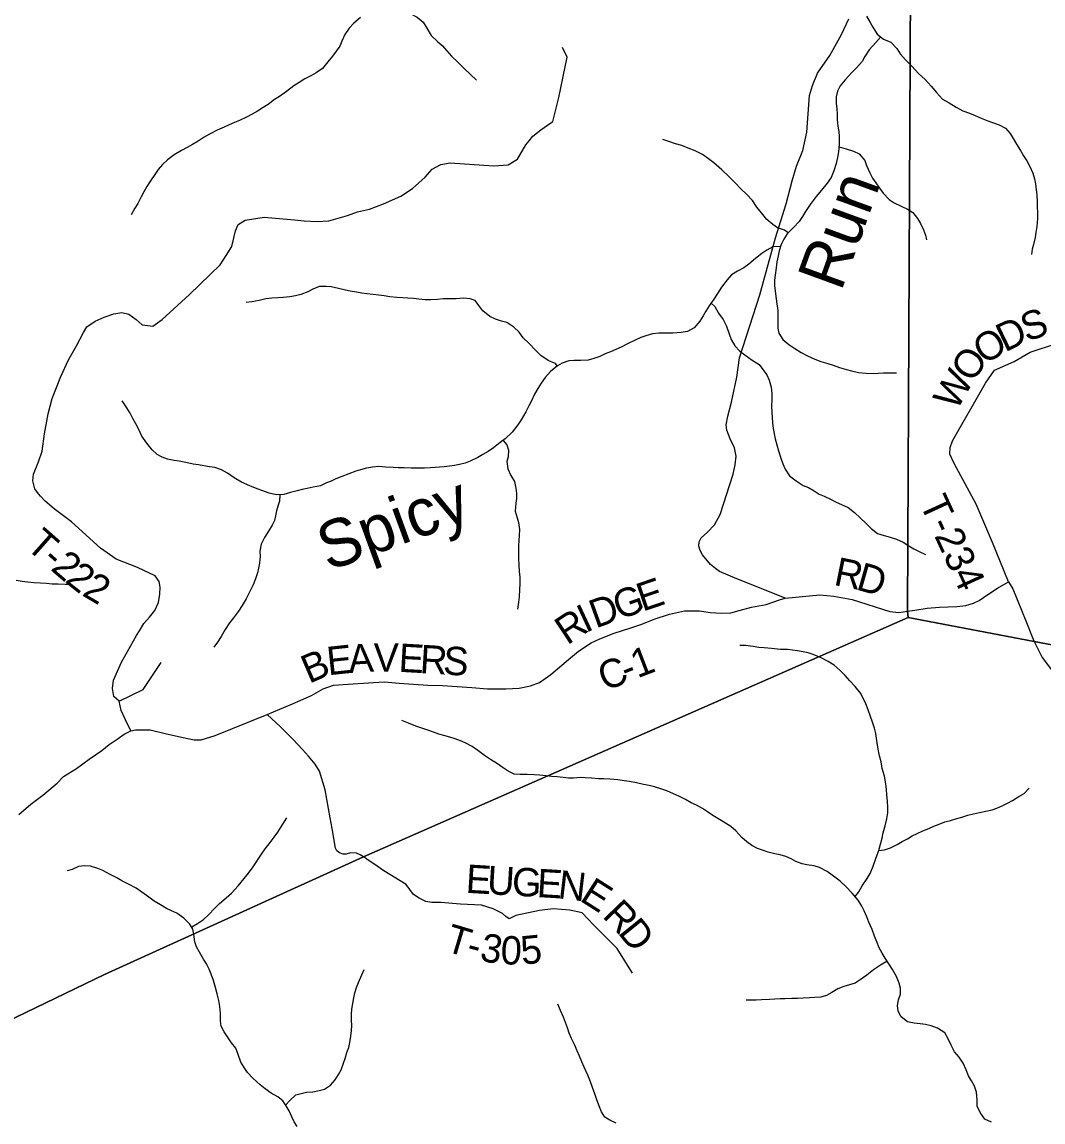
# Model space of a CAD drawing. Extents: x 1578669 to 1989827, y 208020 to 553079.
# Drawn here: x 1757093 to 1767882, y 384601 to 396225 of the extents above; entities that cross this region are included whole.
import ezdxf

# ---------------------------------------------------------------- set-up
doc = ezdxf.new("R2010")
doc.units = 0
for name, color, linetype in [('GM_X_County_Road', 7, 'Continuous'), ('GM_X_County_Road_Text', 7, 'Continuous'), ('GM_X_Minor_River', 7, 'Continuous'), ('GM_X_Minor_River_Text', 7, 'Continuous'), ('GM_X_Township', 7, 'Continuous'), ('GM_X_Township_Road', 7, 'Continuous'), ('GM_X_Township_Road_Text', 7, 'Continuous'), ('GM_X_Township_ROW', 7, 'Continuous')]:
    doc.layers.add(name, color=color, linetype=linetype)

msp = doc.modelspace()

# ---------------------------------------------------------------- linework, layer by layer
at = {"layer": 'GM_X_County_Road'}
for points in [[(1766527, 390011), (1766658, 390031), (1766789, 390041), (1766973, 390047), (1767065, 390058), (1767149, 390084), (1767208, 390113), (1767298, 390174), (1767402, 390241), (1767517, 390309), (1767563, 390236), (1767699, 389896), (1767767, 389729)], [(1757061, 387849), (1757185, 387958), (1757312, 388055), (1757463, 388183), (1757532, 388253), (1757669, 388337), (1757804, 388434), (1757935, 388527), (1758014, 388590), (1758099, 388647), (1758171, 388701), (1758215, 388722), (1758242, 388734), (1758294, 388746), (1758446, 388746), (1758619, 388702), (1758797, 388664), (1758911, 388640), (1758987, 388639), (1759135, 388684), (1759685, 388906), (1759952, 389021), (1760151, 389109), (1760277, 389178), (1760384, 389217), (1760540, 389229), (1760808, 389246), (1760923, 389251), (1761079, 389239), (1761381, 389218), (1761535, 389212), (1761847, 389192), (1762012, 389178), (1762207, 389178), (1762347, 389186), (1762465, 389209), (1762562, 389246), (1762682, 389329), (1762868, 389489), (1762973, 389578), (1763106, 389663), (1763199, 389708), (1763349, 389765), (1763516, 389819), (1763643, 389862), (1763773, 389914), (1763936, 389967), (1764094, 390001), (1764253, 390001), (1764366, 389986), (1764484, 389978), (1764583, 389983), (1764671, 390006), (1764801, 390041), (1764956, 390069), (1765098, 390120), (1765159, 390135), (1765341, 390155), (1765523, 390171), (1765673, 390159), (1765867, 390121), (1766264, 389996), (1766358, 389985), (1766452, 389999), (1766527, 390011)], [(1767767, 389729), (1767788, 389678), (1767875, 389511), (1767972, 389378), (1768053, 389292), (1768114, 389256), (1768276, 389190), (1768452, 389138), (1768590, 389116), (1768649, 389123), (1768926, 389190), (1769160, 389267), (1769361, 389336)]]:
    msp.add_lwpolyline(points, dxfattribs=at)
at = {"layer": 'GM_X_Minor_River'}
for points in [[(1760817, 396602), (1760844, 396579), (1760894, 396526), (1760956, 396470), (1761011, 396418), (1761077, 396384), (1761131, 396349), (1761203, 396311), (1761269, 396277), (1761332, 396222), (1761372, 396158), (1761416, 396082), (1761484, 396017), (1761537, 395973), (1761583, 395921), (1761633, 395865), (1761699, 395802), (1761765, 395734), (1761896, 395609)], [(1760669, 396273), (1760599, 396211), (1760549, 396161), (1760505, 396093), (1760474, 396021), (1760450, 395969), (1760414, 395915), (1760374, 395863), (1760326, 395803), (1760268, 395735), (1760202, 395689), (1760151, 395659), (1760083, 395625), (1760021, 395585), (1759965, 395549), (1759887, 395492), (1759813, 395436), (1759761, 395406), (1759693, 395352), (1759641, 395322), (1759581, 395284), (1759525, 395252), (1759467, 395220), (1759392, 395184), (1759340, 395163), (1759282, 395137), (1759230, 395115), (1759154, 395083), (1759074, 395041), (1759018, 395009), (1758956, 394967), (1758894, 394930), (1758840, 394900), (1758778, 394866), (1758700, 394822), (1758632, 394770), (1758576, 394718), (1758533, 394666), (1758495, 394614), (1758451, 394546), (1758413, 394486), (1758379, 394430), (1758353, 394378), (1758316, 394308), (1758286, 394256), (1758248, 394188)], [(1766017, 396287), (1766055, 396219), (1766083, 396169), (1766128, 396097), (1766198, 396042), (1766274, 396012), (1766338, 395946), (1766373, 395887), (1766429, 395825), (1766497, 395759), (1766565, 395682), (1766638, 395616), (1766700, 395546), (1766756, 395479), (1766821, 395409), (1766891, 395369), (1766963, 395324), (1767035, 395286), (1767105, 395262), (1767165, 395238), (1767230, 395207), (1767298, 395179), (1767350, 395161), (1767418, 395137), (1767486, 395102), (1767536, 395048), (1767567, 394992), (1767603, 394934), (1767645, 394867), (1767677, 394809), (1767711, 394759), (1767744, 394697), (1767774, 394626), (1767794, 394566), (1767802, 394516), (1767811, 394452), (1767817, 394400), (1767821, 394324), (1767821, 394272), (1767825, 394209), (1767824, 394149), (1767818, 394065), (1767808, 394001), (1767798, 393947), (1767780, 393875), (1767769, 393825), (1767761, 393767)], [(1766167, 396067), (1766116, 396009), (1766046, 395929), (1766000, 395859), (1765971, 395809), (1765911, 395741), (1765861, 395691), (1765791, 395613), (1765739, 395551), (1765711, 395495), (1765698, 395435), (1765696, 395367), (1765702, 395306), (1765706, 395250), (1765708, 395192), (1765715, 395124), (1765723, 395066), (1765729, 395014), (1765729, 394932), (1765722, 394853), (1765712, 394793), (1765698, 394731), (1765672, 394651), (1765644, 394583), (1765603, 394521), (1765541, 394449), (1765485, 394381), (1765421, 394295), (1765373, 394223), (1765340, 394171), (1765306, 394115), (1765244, 394053), (1765180, 393987), (1765144, 393929), (1765116, 393873), (1765095, 393807), (1765083, 393755), (1765071, 393689), (1765063, 393627), (1765053, 393551), (1765046, 393495), (1765046, 393441), (1765056, 393353), (1765064, 393300), (1765070, 393248), (1765081, 393176), (1765081, 393124), (1765079, 393056), (1765079, 392990), (1765089, 392936), (1765132, 392869), (1765196, 392817), (1765260, 392775), (1765328, 392734), (1765392, 392698), (1765471, 392662), (1765533, 392638), (1765607, 392615), (1765665, 392597), (1765733, 392573), (1765805, 392553), (1765857, 392540), (1765931, 392522), (1766012, 392514), (1766088, 392512), (1766140, 392513), (1766196, 392517), (1766334, 392517)], [(1765189, 393997), (1765150, 394024), (1765078, 394050), (1765026, 394084), (1764963, 394138), (1764907, 394207), (1764859, 394269), (1764811, 394337), (1764750, 394404), (1764694, 394460), (1764626, 394530), (1764561, 394591), (1764489, 394663), (1764403, 394735), (1764347, 394780), (1764284, 394826), (1764208, 394864), (1764134, 394893), (1764064, 394919), (1764000, 394939), (1763928, 394961), (1763864, 394984)], [(1765727, 394907), (1765803, 394883), (1765880, 394859), (1765938, 394831), (1765998, 394762), (1766018, 394710), (1766053, 394630), (1766081, 394576), (1766117, 394526), (1766155, 394469), (1766193, 394417), (1766256, 394349), (1766308, 394314), (1766384, 394278), (1766450, 394248), (1766508, 394210), (1766555, 394147), (1766589, 394097), (1766621, 394027), (1766639, 393973), (1766651, 393923)], [(1765109, 393851), (1765028, 393850), (1764964, 393812), (1764912, 393780), (1764843, 393724), (1764773, 393666), (1764721, 393626), (1764653, 393592), (1764591, 393554), (1764545, 393500), (1764485, 393421), (1764442, 393357), (1764404, 393295), (1764356, 393227), (1764320, 393169), (1764292, 393119), (1764256, 393063), (1764197, 392993), (1764127, 392953), (1764059, 392943), (1763971, 392935), (1763905, 392937), (1763824, 392938), (1763756, 392928), (1763684, 392910), (1763634, 392890), (1763574, 392864), (1763497, 392826), (1763423, 392787), (1763369, 392765), (1763311, 392741), (1763257, 392717), (1763199, 392691), (1763137, 392669), (1763077, 392652), (1762997, 392648), (1762929, 392648), (1762873, 392644), (1762801, 392620), (1762751, 392592), (1762679, 392533), (1762621, 392469), (1762579, 392409), (1762543, 392351), (1762510, 392291), (1762476, 392221), (1762450, 392169), (1762416, 392105), (1762368, 392021), (1762333, 391967), (1762271, 391889), (1762197, 391821), (1762147, 391781), (1762075, 391725), (1762019, 391687), (1761963, 391653), (1761909, 391623), (1761829, 391583), (1761775, 391562), (1761715, 391550), (1761663, 391540), (1761609, 391532), (1761553, 391524), (1761409, 391513), (1761347, 391511), (1761287, 391511), (1761207, 391509), (1761131, 391512), (1761071, 391514), (1761015, 391516), (1760935, 391522), (1760863, 391528), (1760795, 391521), (1760733, 391509), (1760669, 391493), (1760619, 391477), (1760547, 391449), (1760471, 391422), (1760411, 391396), (1760361, 391374), (1760311, 391356), (1760249, 391324), (1760171, 391310), (1760105, 391296), (1760053, 391283), (1760001, 391271), (1759931, 391253), (1759859, 391233), (1759781, 391227), (1759705, 391246), (1759639, 391270), (1759579, 391292), (1759500, 391322), (1759414, 391361), (1759334, 391409), (1759264, 391458), (1759200, 391494), (1759132, 391516), (1759075, 391524), (1759015, 391534), (1758957, 391545)], [(1762749, 392591), (1762729, 392615), (1762661, 392643), (1762580, 392697), (1762516, 392760), (1762454, 392826), (1762390, 392886), (1762345, 392946), (1762291, 392999), (1762215, 393051), (1762159, 393065), (1762095, 393084), (1762038, 393114), (1761964, 393172), (1761922, 393230), (1761882, 393281), (1761830, 393301), (1761758, 393307), (1761680, 393301), (1761622, 393299), (1761545, 393298), (1761485, 393292), (1761409, 393288), (1761355, 393288), (1761285, 393297), (1761231, 393303), (1761169, 393307), (1761117, 393309), (1761055, 393315), (1760979, 393322), (1760921, 393330), (1760865, 393338), (1760805, 393344), (1760737, 393352), (1760683, 393359), (1760627, 393369), (1760562, 393379), (1760510, 393391), (1760436, 393409), (1760360, 393426), (1760308, 393430), (1760238, 393430), (1760172, 393406), (1760114, 393374), (1760038, 393347), (1759982, 393331), (1759922, 393321), (1759852, 393315), (1759798, 393311), (1759734, 393308), (1759668, 393298), (1759598, 393282), (1759522, 393268), (1759460, 393262)], [(1764375, 393254), (1764414, 393218), (1764454, 393148), (1764501, 393080), (1764537, 393010), (1764567, 392931), (1764587, 392871), (1764626, 392803), (1764678, 392747), (1764730, 392706), (1764810, 392652), (1764884, 392604), (1764923, 392553), (1764963, 392495), (1764989, 392441), (1765009, 392365), (1765016, 392299), (1765016, 392234), (1765014, 392164), (1765016, 392100), (1765020, 392046), (1765025, 391990), (1765031, 391930), (1765053, 391820), (1765088, 391693), (1765110, 391615), (1765134, 391555), (1765156, 391501), (1765203, 391430), (1765273, 391376), (1765349, 391326), (1765403, 391306), (1765465, 391271), (1765517, 391237), (1765568, 391215), (1765644, 391180), (1765698, 391152), (1765754, 391126), (1765822, 391096), (1765890, 391041), (1765951, 390985), (1766015, 390925), (1766067, 390873), (1766135, 390820), (1766203, 390800), (1766268, 390782), (1766334, 390760), (1766404, 390727), (1766466, 390689), (1766518, 390657), (1766572, 390631), (1766642, 390598)], [(1758957, 391545), (1758903, 391553), (1758825, 391571), (1758753, 391585), (1758701, 391592), (1758631, 391606), (1758573, 391626), (1758521, 391654), (1758468, 391705), (1758412, 391775), (1758360, 391847), (1758330, 391913), (1758297, 391980), (1758265, 392036), (1758237, 392090), (1758193, 392158), (1758150, 392221)], [(1762176, 391804), (1762217, 391755), (1762235, 391700), (1762230, 391630), (1762218, 391580), (1762228, 391504), (1762260, 391432), (1762296, 391368), (1762313, 391299), (1762319, 391243), (1762317, 391191), (1762311, 391139), (1762306, 391055), (1762326, 390987), (1762340, 390935), (1762350, 390862), (1762348, 390800), (1762343, 390746), (1762341, 390688), (1762341, 390556), (1762343, 390484), (1762348, 390418), (1762354, 390360), (1762354, 390287), (1762350, 390227), (1762347, 390149), (1762341, 390093), (1762329, 390021)], [(1759817, 391230), (1759813, 391161), (1759795, 391109), (1759782, 391059), (1759770, 391007), (1759760, 390957), (1759736, 390907), (1759698, 390845), (1759656, 390779), (1759621, 390707), (1759607, 390633), (1759609, 390577), (1759601, 390505), (1759593, 390455), (1759580, 390403), (1759562, 390342), (1759536, 390278), (1759504, 390214), (1759460, 390128), (1759421, 390060), (1759379, 389998), (1759327, 389927), (1759287, 389875), (1759241, 389805), (1759196, 389731), (1759160, 389671), (1759120, 389619)], [(1757030, 390325), (1757094, 390316), (1757152, 390310), (1757218, 390302), (1757288, 390298), (1757352, 390294), (1757410, 390289), (1757476, 390287), (1757550, 390285), (1757616, 390281)], [(1765896, 386984), (1765936, 387034), (1765972, 387098), (1766025, 387174), (1766055, 387226), (1766087, 387306), (1766119, 387396), (1766146, 387470), (1766164, 387538), (1766182, 387600), (1766194, 387656), (1766216, 387730), (1766231, 387806), (1766241, 387867), (1766243, 387927), (1766239, 387991), (1766233, 388057), (1766230, 388115), (1766222, 388173), (1766208, 388257), (1766184, 388336), (1766171, 388406), (1766153, 388472), (1766143, 388522), (1766135, 388582), (1766124, 388656), (1766114, 388706), (1766100, 388763), (1766082, 388825), (1766058, 388887), (1766033, 388955), (1766011, 389019), (1765957, 389128), (1765896, 389202), (1765840, 389264), (1765790, 389319), (1765738, 389373), (1765674, 389429), (1765613, 389469), (1765537, 389506), (1765453, 389542), (1765399, 389560), (1765347, 389568), (1765289, 389581), (1765235, 389587), (1765183, 389593), (1765109, 389595), (1765012, 389604), (1764934, 389610), (1764880, 389616), (1764820, 389624), (1764740, 389637), (1764678, 389635)], [(1763660, 388167), (1763586, 388184), (1763512, 388198), (1763456, 388208), (1763388, 388216), (1763306, 388223), (1763242, 388227), (1763184, 388229), (1763110, 388235), (1763045, 388238), (1762991, 388240), (1762921, 388236), (1762869, 388236), (1762811, 388240), (1762747, 388247), (1762687, 388251), (1762631, 388259), (1762561, 388265), (1762505, 388269), (1762431, 388274), (1762357, 388274), (1762295, 388278), (1762229, 388308), (1762168, 388351), (1762116, 388387), (1762044, 388431), (1761980, 388475), (1761910, 388526), (1761851, 388568), (1761777, 388608), (1761725, 388630), (1761671, 388649), (1761615, 388667), (1761551, 388685), (1761499, 388699), (1761443, 388720), (1761392, 388738), (1761328, 388760), (1761254, 388784), (1761178, 388817), (1761108, 388843)], [(1767337, 384599), (1767269, 384631), (1767218, 384700), (1767188, 384770), (1767186, 384834), (1767180, 384916), (1767157, 384980), (1767127, 385036), (1767095, 385089), (1767071, 385151), (1767039, 385223), (1766996, 385287), (1766948, 385344), (1766912, 385414), (1766876, 385488), (1766845, 385542), (1766769, 385593), (1766699, 385617), (1766639, 385633), (1766585, 385637), (1766521, 385644), (1766449, 385660), (1766384, 385712), (1766352, 385774), (1766346, 385832), (1766356, 385893), (1766376, 385953), (1766375, 386015), (1766363, 386067), (1766333, 386139), (1766293, 386211), (1766261, 386262), (1766214, 386332), (1766184, 386384), (1766148, 386448), (1766128, 386498), (1766103, 386565), (1766077, 386635), (1766043, 386713), (1766019, 386769), (1765992, 386831), (1765966, 386882), (1765928, 386946), (1765866, 387020), (1765801, 387085), (1765739, 387147), (1765653, 387209), (1765601, 387248), (1765519, 387292), (1765464, 387308), (1765388, 387320), (1765336, 387328), (1765272, 387355), (1765220, 387383), (1765164, 387407), (1765104, 387425), (1765050, 387436), (1764978, 387454), (1764919, 387472), (1764865, 387492), (1764805, 387523), (1764753, 387563), (1764701, 387609), (1764635, 387679), (1764584, 387722), (1764528, 387760), (1764464, 387798), (1764394, 387840), (1764336, 387879), (1764285, 387913), (1764219, 387949), (1764165, 387975), (1764105, 388010), (1764035, 388044), (1763979, 388068), (1763907, 388100), (1763854, 388119), (1763778, 388143), (1763720, 388157), (1763660, 388167)], [(1766145, 387469), (1766208, 387478), (1766272, 387500), (1766342, 387532), (1766394, 387564), (1766450, 387595), (1766500, 387625), (1766554, 387651), (1766612, 387677), (1766676, 387703), (1766730, 387727), (1766784, 387747), (1766846, 387772), (1766906, 387786), (1766972, 387808), (1767024, 387824), (1767088, 387842), (1767148, 387856), (1767210, 387871), (1767278, 387887), (1767344, 387901), (1767396, 387917), (1767456, 387945), (1767506, 387969), (1767560, 387999), (1767628, 388042), (1767682, 388074), (1767736, 388128)], [(1758886, 386662), (1758947, 386700), (1759011, 386740), (1759065, 386790), (1759131, 386860), (1759181, 386910), (1759249, 386970), (1759305, 387020), (1759378, 387097), (1759442, 387173), (1759488, 387231), (1759536, 387299), (1759625, 387431), (1759663, 387487), (1759705, 387541), (1759757, 387611), (1759795, 387665), (1759849, 387749), (1759890, 387817)], [(1758673, 386833), (1758621, 386858), (1758556, 386896), (1758488, 386934), (1758434, 386976), (1758360, 387031), (1758298, 387073), (1758219, 387115), (1758149, 387148), (1758095, 387182), (1758025, 387216), (1757947, 387258), (1757893, 387281), (1757816, 387303), (1757754, 387307), (1757690, 387301), (1757624, 387271), (1757570, 387256)], [(1760001, 384553), (1759969, 384603), (1759943, 384655), (1759915, 384719), (1759884, 384772), (1759850, 384824), (1759796, 384866), (1759726, 384906), (1759662, 384953), (1759611, 384995), (1759533, 385065), (1759475, 385124), (1759441, 385176), (1759405, 385232), (1759378, 385314), (1759354, 385383), (1759306, 385439), (1759270, 385491), (1759229, 385553), (1759197, 385613), (1759189, 385670), (1759189, 385752), (1759182, 385820), (1759172, 385884), (1759156, 385956), (1759138, 386024), (1759117, 386095), (1759091, 386165), (1759069, 386217), (1759041, 386273), (1759011, 386323), (1758968, 386396), (1758938, 386452), (1758920, 386506), (1758908, 386586), (1758899, 386640), (1758867, 386692), (1758803, 386755), (1758729, 386807), (1758673, 386833)], [(1766235, 386301), (1766166, 386260), (1766091, 386210), (1766021, 386152), (1765951, 386102), (1765899, 386070), (1765839, 386051), (1765779, 386033), (1765715, 386009), (1765649, 385971), (1765595, 385939), (1765535, 385919), (1765467, 385916), (1765413, 385914), (1765349, 385910), (1765289, 385906), (1765227, 385906), (1765155, 385903), (1765103, 385901), (1765049, 385899), (1764991, 385897), (1764907, 385891), (1764851, 385889), (1764799, 385888), (1764745, 385888)], [(1759878, 384780), (1759924, 384830), (1759988, 384890), (1760044, 384903), (1760100, 384915), (1760166, 384921), (1760234, 384933), (1760290, 384949), (1760354, 384991), (1760402, 385048), (1760438, 385102), (1760464, 385154), (1760491, 385223), (1760509, 385273), (1760525, 385335), (1760545, 385387), (1760557, 385443), (1760568, 385507), (1760574, 385569), (1760578, 385621), (1760574, 385673), (1760576, 385741), (1760580, 385793), (1760589, 385853), (1760599, 385913), (1760611, 385967), (1760627, 386024), (1760649, 386074), (1760710, 386214)], [(1763370, 384590), (1763304, 384620), (1763253, 384654), (1763215, 384709), (1763195, 384761), (1763167, 384837), (1763147, 384899), (1763122, 384967), (1763102, 385026), (1763072, 385096), (1763032, 385182), (1763009, 385238), (1762983, 385298), (1762959, 385353), (1762931, 385421), (1762900, 385483), (1762876, 385539), (1762856, 385597), (1762836, 385654), (1762816, 385708), (1762785, 385780), (1762755, 385848)]]:
    msp.add_lwpolyline(points, dxfattribs=at)
at = {"layer": 'GM_X_Township'}
for points in [[(1766495, 399541), (1766452, 389999), (1766457, 389933), (1760700, 387403), (1757963, 386161), (1756930, 385658), (1755534, 385267), (1753423, 384881), (1752837, 384779), (1752746, 384750), (1752525, 384707), (1752358, 384675), (1752267, 384661), (1743250, 382913)], [(1769444, 389364), (1767788, 389678), (1766457, 389933), (1766452, 389999), (1766495, 399541)], [(1743250, 382913), (1752267, 384661), (1752358, 384675), (1752525, 384707), (1752746, 384750), (1752837, 384779), (1753423, 384881), (1755534, 385267), (1756930, 385658), (1757963, 386161), (1760700, 387403), (1766457, 389933), (1767788, 389678), (1769444, 389364)]]:
    msp.add_lwpolyline(points, dxfattribs=at)
at = {"layer": 'GM_X_Township_Road'}
for points in [[(1762453, 394970), (1762453, 394970), (1762491, 395017), (1762574, 395084), (1762645, 395134), (1762701, 395173), (1762739, 395313), (1762766, 395427), (1762853, 395854), (1762806, 395955)], [(1757270, 391237), (1757269, 391238), (1757228, 391293), (1757207, 391376), (1757214, 391446), (1757269, 391576), (1757305, 391690), (1757331, 391872), (1757369, 392084), (1757413, 392246), (1757503, 392480), (1757585, 392656), (1757669, 392803), (1757744, 392943), (1757779, 393005), (1757866, 393064), (1757960, 393107), (1758063, 393142), (1758149, 393155), (1758221, 393136), (1758298, 393081), (1758364, 393026), (1758476, 393009), (1758574, 393080), (1758863, 393347), (1759187, 393659), (1759252, 393758), (1759309, 393854), (1759349, 394018), (1759378, 394086), (1759450, 394131), (1759653, 394163), (1759971, 394135), (1760076, 394124), (1760212, 394118), (1760335, 394125), (1760531, 394179), (1760640, 394220), (1760764, 394246), (1760913, 394303), (1761096, 394385), (1761219, 394466), (1761352, 394585), (1761427, 394670), (1761518, 394719), (1761618, 394738), (1762076, 394705), (1762232, 394717), (1762329, 394776), (1762418, 394928), (1762453, 394970)], [(1767517, 390309), (1767347, 390724), (1767177, 391129), (1766945, 391561), (1766899, 391658), (1766900, 391728), (1766925, 391798), (1767275, 392408), (1767369, 392544), (1767578, 392638), (1767748, 392736), (1768026, 392827), (1768248, 392923), (1768484, 393083), (1768705, 393239), (1768872, 393349), (1769009, 393352), (1769921, 393351)], [(1758242, 388734), (1758187, 388851), (1758142, 388948), (1758118, 389047), (1758065, 389099), (1758048, 389182), (1758059, 389270), (1758145, 389459), (1758302, 389742), (1758335, 389792), (1758382, 389870), (1758439, 389937), (1758495, 390007), (1758536, 390091), (1758549, 390177), (1758554, 390251), (1758543, 390311), (1758501, 390372), (1758314, 390462), (1758087, 390549), (1757922, 390664), (1757615, 390944), (1757434, 391080), (1757339, 391160), (1757288, 391213), (1757270, 391237)], [(1765159, 390135), (1764868, 390251), (1764648, 390340), (1764465, 390418), (1764423, 390450)], [(1758118, 389047), (1758373, 389171), (1758565, 389456)], [(1760741, 387376), (1760732, 387382), (1760700, 387403), (1760668, 387425), (1760629, 387442), (1760565, 387445), (1760517, 387430), (1760487, 387430), (1760448, 387444), (1760419, 387468), (1760404, 387495), (1760372, 387702), (1760348, 387816), (1760298, 388110), (1760236, 388307), (1760191, 388382), (1760121, 388467), (1760058, 388536), (1759957, 388642), (1759826, 388776), (1759685, 388906)], [(1763546, 386174), (1763383, 386435), (1763133, 386684), (1763012, 386812), (1762882, 386838), (1762707, 386854), (1762563, 386837), (1762311, 386782), (1762241, 386747), (1762205, 386773), (1762169, 386804), (1762071, 386853), (1761949, 386891), (1761727, 386903), (1761518, 386922), (1761424, 386921), (1761362, 386932), (1761290, 386967), (1761230, 387005), (1761154, 387110), (1760918, 387255), (1760810, 387330), (1760741, 387376)]]:
    msp.add_lwpolyline(points, dxfattribs=at)
at = {"layer": 'GM_X_Township_ROW'}
msp.add_lwpolyline([(1764423, 390450), (1764368, 390491), (1764285, 390595), (1764259, 390639), (1764246, 390687), (1764250, 390733), (1764269, 390773), (1764338, 390833), (1764410, 390912), (1764470, 391022), (1764608, 391448), (1764629, 391544), (1764640, 391636), (1764623, 391724), (1764578, 391821), (1764541, 391910), (1764534, 391968), (1764551, 392060), (1764592, 392208), (1764647, 392472), (1764674, 392677), (1764889, 393342), (1765057, 393944), (1765169, 394302), (1765230, 394546), (1765278, 394700), (1765343, 394868), (1765386, 395062), (1765414, 395447), (1765445, 395553), (1765500, 395683), (1765630, 395872), (1765753, 396093), (1765831, 396257)], dxfattribs=at)

# ---------------------------------------------------------------- texts
at = {"layer": 'GM_X_County_Road_Text'}
for s, rotation, p in [('R', 348.6227, (1765661, 390278)), ('D', 344.0621, (1765896, 390231)), ('E', 18.8754, (1763651, 389992)), ('G', 19.4487, (1763402, 389905)), ('D', 19.8888, (1763155, 389815)), ('R', 33.5764, (1762855, 389635)), ('I', 24.966, (1763049, 389766)), ('E', 6.0193, (1760329, 389321)), ('A', 3.5102, (1760549, 389344)), ('V', 359.7122, (1760807, 389360)), ('E', 356.7541, (1761067, 389359)), ('R', 356.4305, (1761291, 389346)), ('S', 356.4854, (1761537, 389331)), ('B', 23.2714, (1760126, 389230)), ('C', 21.9732, (1763255, 389150)), ('1', 20.9568, (1763596, 389288)), ('-', 21.7768, (1763483, 389242))]:
    msp.add_text(s, height=300, rotation=rotation, dxfattribs=at).set_placement(p)
at = {"layer": 'GM_X_Minor_River_Text'}
for s, rotation, p in [('Run', 69.9991, (1765748, 393368)), ('Spicy', 19.9966, (1760328, 390419))]:
    msp.add_text(s, height=500, rotation=rotation, dxfattribs=at).set_placement(p)
at = {"layer": 'GM_X_Township_Road_Text'}
for s, rotation, p in [('S', 19.5439, (1767710, 392843)), ('D', 25.713, (1767480, 392732)), ('O', 31.03, (1767260, 392599)), ('O', 55.8603, (1767137, 392404)), ('W', 60.5025, (1766969, 392107)), ('T-234', 294.586, (1766573, 391141)), ('T', 318.5508, (1757122, 390673)), ('-', 318.6858, (1757291, 390524)), ('2', 319.23, (1757386, 390441)), ('2', 321.4452, (1757536, 390312)), ('2', 329.3468, (1757717, 390171)), ('E', 356.5953, (1761777, 387024)), ('U', 356.5957, (1762001, 387010)), ('G', 356.5957, (1762264, 386995)), ('E', 356.4835, (1762528, 386979)), ('N', 353.2157, (1762747, 386966)), ('E', 327.5581, (1762976, 386946)), ('R', 314.0175, (1763216, 386772)), ('D', 308.9408, (1763383, 386600)), ('T', 343.4465, (1761551, 386411)), ('3', 349.9578, (1761921, 386307)), ('0', 357.5722, (1762146, 386270)), ('5', 5.6169, (1762377, 386263)), ('-', 345.0354, (1761775, 386345))]:
    msp.add_text(s, height=300, rotation=rotation, dxfattribs=at).set_placement(p)

doc.saveas('drawing.dxf')
